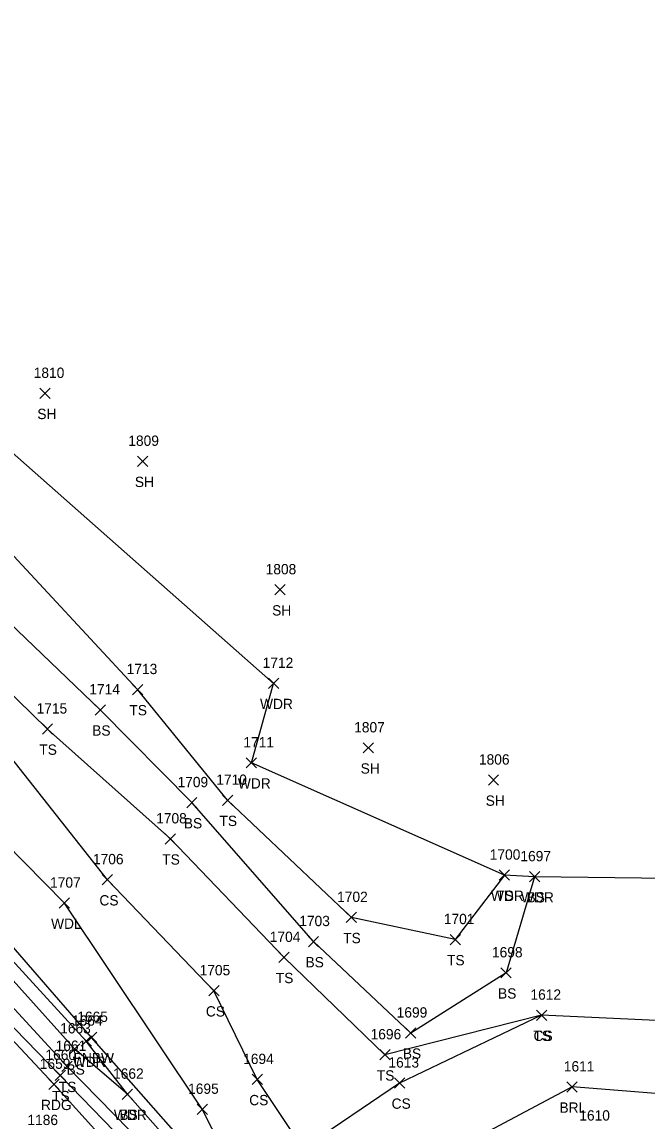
# Model space of a CAD drawing. Extents: x 1469310 to 1475157, y 493997 to 498873.
# Drawn here: x 1469508.8 to 1469630.2, y 498651.4 to 498864.7 of the extents above; entities that cross this region are included whole.
import ezdxf

# ---------------------------------------------------------------- set-up
doc = ezdxf.new("R2010")
doc.units = 0
for name, color, linetype in [('L_A', 7, 'Continuous'), ('L_I', 7, 'Continuous'), ('L_TIC', 7, 'Continuous'), ('LABL', 7, 'Continuous'), ('LAWA', 7, 'Continuous'), ('LELB', 7, 'Continuous'), ('LFNC', 7, 'Continuous'), ('P_A', 7, 'Continuous'), ('P_I', 7, 'Continuous'), ('P_TIC', 7, 'Continuous'), ('PEU', 7, 'Continuous')]:
    doc.layers.add(name, color=color, linetype=linetype)

msp = doc.modelspace()

# ---------------------------------------------------------------- linework, layer by layer
at = {"layer": 'L_TIC'}
for points in [[(1469512.26, 498791.65), (1469514.26, 498793.65)], [(1469514.26, 498791.65), (1469512.26, 498793.65)], [(1469531.21, 498778.46), (1469533.21, 498780.46)], [(1469533.21, 498778.46), (1469531.21, 498780.46)], [(1469557.88, 498753.52), (1469559.88, 498755.52)], [(1469559.88, 498753.52), (1469557.88, 498755.52)], [(1469556.66, 498735.35), (1469558.66, 498737.35)], [(1469558.66, 498735.35), (1469556.66, 498737.35)], [(1469530.24, 498734.14), (1469532.24, 498736.14)], [(1469532.24, 498734.14), (1469530.24, 498736.14)], [(1469522.97, 498730.2), (1469524.97, 498732.2)], [(1469524.97, 498730.2), (1469522.97, 498732.2)], [(1469512.73, 498726.48), (1469514.73, 498728.48)], [(1469514.73, 498726.48), (1469512.73, 498728.48)], [(1469575.08, 498722.83), (1469577.08, 498724.83)], [(1469577.08, 498722.83), (1469575.08, 498724.83)], [(1469552.35, 498719.92), (1469554.35, 498721.92)], [(1469554.35, 498719.92), (1469552.35, 498721.92)], [(1469599.38, 498716.58), (1469601.38, 498718.58)], [(1469601.38, 498716.58), (1469599.38, 498718.58)], [(1469540.77, 498712.19), (1469542.77, 498714.19)], [(1469542.77, 498712.19), (1469540.77, 498714.19)], [(1469547.73, 498712.65), (1469549.73, 498714.65)], [(1469549.73, 498712.65), (1469547.73, 498714.65)], [(1469536.62, 498705.16), (1469538.62, 498707.16)], [(1469538.62, 498705.16), (1469536.62, 498707.16)], [(1469524.38, 498697.23), (1469526.38, 498699.23)], [(1469526.38, 498697.23), (1469524.38, 498699.23)], [(1469601.51, 498698.12), (1469603.51, 498700.12)], [(1469603.51, 498698.12), (1469601.51, 498700.12)], [(1469601.51, 498698.12), (1469603.51, 498700.12)], [(1469603.51, 498698.12), (1469601.51, 498700.12)], [(1469607.35, 498697.81), (1469609.35, 498699.81)], [(1469609.35, 498697.81), (1469607.35, 498699.81)], [(1469607.35, 498697.81), (1469609.35, 498699.81)], [(1469609.35, 498697.81), (1469607.35, 498699.81)], [(1469516, 498692.69), (1469518, 498694.69)], [(1469518, 498692.69), (1469516, 498694.69)], [(1469571.77, 498689.91), (1469573.77, 498691.91)], [(1469573.77, 498689.91), (1469571.77, 498691.91)], [(1469564.41, 498685.22), (1469566.41, 498687.22)], [(1469566.41, 498685.22), (1469564.41, 498687.22)], [(1469591.94, 498685.61), (1469593.94, 498687.61)], [(1469593.94, 498685.61), (1469591.94, 498687.61)], [(1469558.68, 498682.15), (1469560.68, 498684.15)], [(1469560.68, 498682.15), (1469558.68, 498684.15)], [(1469601.82, 498679.15), (1469603.82, 498681.15)], [(1469603.82, 498679.15), (1469601.82, 498681.15)], [(1469545.06, 498675.67), (1469547.06, 498677.67)], [(1469547.06, 498675.67), (1469545.06, 498677.67)], [(1469608.73, 498670.93), (1469610.73, 498672.93)], [(1469610.73, 498670.93), (1469608.73, 498672.93)], [(1469608.73, 498670.93), (1469610.73, 498672.93)], [(1469610.73, 498670.93), (1469608.73, 498672.93)], [(1469583.31, 498667.47), (1469585.31, 498669.47)], [(1469585.31, 498667.47), (1469583.31, 498669.47)], [(1469520.27, 498665.89), (1469522.27, 498667.89)], [(1469522.27, 498665.89), (1469520.27, 498667.89)], [(1469521.29, 498666.62), (1469523.29, 498668.62)], [(1469523.29, 498666.62), (1469521.29, 498668.62)], [(1469517.98, 498664.39), (1469519.98, 498666.39)], [(1469519.98, 498664.39), (1469517.98, 498666.39)], [(1469578.3, 498663.24), (1469580.3, 498665.24)], [(1469580.3, 498663.24), (1469578.3, 498665.24)], [(1469516.52, 498661), (1469518.52, 498663)], [(1469518.52, 498661), (1469516.52, 498663)], [(1469515.21, 498659.23), (1469517.21, 498661.23)], [(1469517.21, 498659.23), (1469515.21, 498661.23)], [(1469553.48, 498658.45), (1469555.48, 498660.45)], [(1469555.48, 498658.45), (1469553.48, 498660.45)], [(1469581.14, 498657.76), (1469583.14, 498659.76)], [(1469583.14, 498657.76), (1469581.14, 498659.76)], [(1469614.65, 498657), (1469616.65, 498659)], [(1469616.65, 498657), (1469614.65, 498659)], [(1469528.26, 498655.59), (1469530.26, 498657.59)], [(1469530.26, 498655.59), (1469528.26, 498657.59)], [(1469528.26, 498655.59), (1469530.26, 498657.59)], [(1469530.26, 498655.59), (1469528.26, 498657.59)], [(1469542.79, 498652.66), (1469544.79, 498654.66)], [(1469544.79, 498652.66), (1469542.79, 498654.66)]]:
    msp.add_lwpolyline(points, dxfattribs=at)
at = {"layer": 'LABL'}
msp.add_lwpolyline([(1469804.95, 498565.12), (1469764.81, 498561.66), (1469749.08, 498576.22), (1469733.12, 498600.55), (1469716.5, 498617.67), (1469685.26, 498643.73), (1469661.91, 498654.33), (1469615.65, 498658), (1469588.27, 498643.44), (1469563.61, 498633.27)], dxfattribs=at)
at = {"layer": 'LAWA'}
for points in [[(1469639.57, 498698.43), (1469608.35, 498698.81), (1469602.51, 498699.12), (1469553.35, 498720.92), (1469557.66, 498736.35), (1469502.31, 498785.09), (1469489.42, 498793.62), (1469479.51, 498786.07), (1469473.54, 498782.36), (1469463.54, 498781.5), (1469427.61, 498811.79), (1469409.37, 498828.74), (1469393.62, 498848.43), (1469395.42, 498864.75)], [(1469550.26, 498635.87), (1469551.34, 498638.82), (1469543.79, 498653.66), (1469517, 498693.69), (1469493.7, 498717.29), (1469464.73, 498743.89), (1469442.45, 498767.36), (1469415.63, 498791.26), (1469396.51, 498809.17), (1469374.23, 498838.07)], [(1469550.26, 498635.87), (1469544.55, 498639.35), (1469529.26, 498656.59), (1469521.27, 498666.89), (1469499.1, 498691), (1469482.91, 498705.54), (1469469.32, 498718.6), (1469451.08, 498739.43), (1469431.27, 498758.58), (1469415.67, 498776.75), (1469392.18, 498799.73), (1469384.54, 498811.21)]]:
    msp.add_lwpolyline(points, dxfattribs=at)
at = {"layer": 'LELB'}
for points in [[(1469609.73, 498671.93), (1469579.3, 498664.24), (1469559.68, 498683.15), (1469537.62, 498706.16), (1469513.73, 498727.48), (1469478.41, 498761.91), (1469463.54, 498781.5), (1469454.7, 498803.05), (1469446.9, 498829.88), (1469451.16, 498846.1)], [(1469689.87, 498657.87), (1469664.2, 498669.39), (1469609.73, 498671.93), (1469582.14, 498658.76), (1469563.4, 498646.02), (1469554.48, 498659.45), (1469546.06, 498676.67), (1469525.38, 498698.23), (1469503.85, 498725.44), (1469472.45, 498754.54), (1469455.13, 498777.29), (1469419.87, 498802.33), (1469400.99, 498819.04), (1469383.05, 498844.76)], [(1469608.35, 498698.81), (1469602.82, 498680.15), (1469584.31, 498668.47), (1469565.41, 498686.22), (1469541.77, 498713.19), (1469523.97, 498731.2), (1469486.88, 498766.71), (1469473.54, 498782.36), (1469464.69, 498810.88), (1469465.59, 498843.26)], [(1469596.34, 498559.71), (1469578.35, 498585.4), (1469563.74, 498607.63), (1469555.37, 498620.37), (1469550.82, 498626.65), (1469541.68, 498637.32), (1469517.52, 498662), (1469494.24, 498687.27), (1469477.2, 498705.84), (1469448.36, 498735.3), (1469427.59, 498756.34), (1469413.62, 498771.3), (1469390.02, 498797.18), (1469364.14, 498823.89)], [(1469563.74, 498607.63), (1469555.09, 498616.5), (1469548.65, 498625.25), (1469539.23, 498636.49), (1469516.21, 498660.23), (1469492, 498685.05), (1469474.24, 498704.18), (1469446.06, 498733.49), (1469425.87, 498754.55), (1469411.99, 498769.1), (1469387.95, 498794.99), (1469362.09, 498822.05)], [(1469602.51, 498699.12), (1469592.94, 498686.61), (1469572.77, 498690.91), (1469548.73, 498713.65), (1469531.24, 498735.14), (1469494.62, 498774.5), (1469479.51, 498786.07)], [(1469529.26, 498656.59), (1469518.98, 498665.39), (1469497.29, 498689.45), (1469482.91, 498705.54)]]:
    msp.add_lwpolyline(points, dxfattribs=at)
at = {"layer": 'LFNC'}
msp.add_lwpolyline([(1469557.57, 498626.92), (1469550.26, 498635.87), (1469522.29, 498667.62), (1469500.25, 498692.91), (1469472.78, 498720.33), (1469454.31, 498738.91), (1469435.59, 498759.19), (1469416.3, 498780.92), (1469395.2, 498801.33), (1469384.54, 498811.21), (1469367.12, 498829.45)], dxfattribs=at)
at = {"layer": 'P_TIC'}
for points in [[(1469513.98, 498657.51), (1469515.98, 498659.51)], [(1469515.98, 498657.51), (1469513.98, 498659.51)]]:
    msp.add_lwpolyline(points, dxfattribs=at)
at = {"layer": 'PEU'}
msp.add_lwpolyline([(1469787.29, 498391.19), (1469770.79, 498403.19), (1469744.94, 498420.51), (1469711.23, 498443.77), (1469680.07, 498463.21), (1469651.58, 498483.41), (1469630.63, 498501.52), (1469612.52, 498523.24), (1469599.41, 498542.19), (1469591.57, 498556.6), (1469575.61, 498583.06), (1469557.31, 498607.49), (1469540.09, 498628.65), (1469536.24, 498634.99), (1469514.98, 498658.51), (1469490.83, 498684.27), (1469472.69, 498702.57), (1469444.89, 498732.16), (1469424.97, 498753.74), (1469411.28, 498767.74), (1469386.83, 498794.07), (1469360.47, 498820.44)], dxfattribs=at)

# ---------------------------------------------------------------- texts
at = {"layer": 'L_A'}
for s, p in [('SH', (1469511.75, 498787.65)), ('SH', (1469530.7, 498774.46)), ('SH', (1469557.37, 498749.52)), ('WDR', (1469555.02, 498731.35)), ('TS', (1469529.64, 498730.14)), ('BS', (1469522.41, 498726.2)), ('TS', (1469512.14, 498722.48)), ('SH', (1469574.57, 498718.83)), ('WDR', (1469550.71, 498715.92)), ('SH', (1469598.86, 498712.58)), ('BS', (1469540.21, 498708.19)), ('TS', (1469547.14, 498708.65)), ('TS', (1469536.02, 498701.16)), ('CS', (1469523.82, 498693.23)), ('WDR', (1469599.87, 498694.12)), ('TS', (1469600.92, 498694.12)), ('WDR', (1469605.72, 498693.81)), ('BS', (1469606.8, 498693.81)), ('WDL', (1469514.42, 498688.69)), ('TS', (1469571.18, 498685.91)), ('BS', (1469563.85, 498681.22)), ('TS', (1469591.35, 498681.61)), ('TS', (1469558.09, 498678.15)), ('BS', (1469601.26, 498675.15)), ('CS', (1469544.5, 498671.67)), ('TS', (1469608.14, 498666.93)), ('CS', (1469608.17, 498666.93)), ('FNBW', (1469518.77, 498662.62)), ('BS', (1469582.76, 498663.47)), ('WDR', (1469518.63, 498661.89)), ('BS', (1469517.42, 498660.39)), ('TS', (1469577.71, 498659.24)), ('TS', (1469515.93, 498657)), ('TS', (1469514.62, 498655.23)), ('CS', (1469552.92, 498654.45)), ('CS', (1469580.59, 498653.76)), ('BRL', (1469613.19, 498653)), ('WDR', (1469526.62, 498651.59)), ('BS', (1469527.7, 498651.59))]:
    msp.add_text(s, height=2, dxfattribs=at).set_placement(p)
at = {"layer": 'L_I'}
for s, p in [('1810', (1469511.05, 498795.65)), ('1809', (1469529.43, 498782.46)), ('1808', (1469556.11, 498757.52)), ('1713', (1469529.11, 498738.14)), ('1712', (1469555.53, 498739.35)), ('1714', (1469521.85, 498734.2)), ('1715', (1469511.6, 498730.48)), ('1807', (1469573.31, 498726.83)), ('1711', (1469551.79, 498723.92)), ('1806', (1469597.55, 498720.58)), ('1709', (1469538.99, 498716.19)), ('1710', (1469546.52, 498716.65)), ('1708', (1469534.84, 498709.16)), ('1706', (1469522.56, 498701.23)), ('1700', (1469599.65, 498702.12)), ('1700', (1469599.65, 498702.12)), ('1697', (1469605.61, 498701.81)), ('1697', (1469605.61, 498701.81)), ('1707', (1469514.23, 498696.69)), ('1702', (1469570, 498693.91)), ('1703', (1469562.64, 498689.22)), ('1701', (1469590.73, 498689.61)), ('1704', (1469556.91, 498686.15)), ('1698', (1469600.08, 498683.15)), ('1705', (1469543.28, 498679.67)), ('1612', (1469607.56, 498674.93)), ('1612', (1469607.56, 498674.93)), ('1699', (1469581.57, 498671.47)), ('1664', (1469518.48, 498669.89)), ('1665', (1469519.51, 498670.62)), ('1663', (1469516.19, 498668.39)), ('1696', (1469576.5, 498667.24)), ('1661', (1469515.3, 498665)), ('1660', (1469513.33, 498663.23)), ('1694', (1469551.74, 498662.45)), ('1613', (1469579.97, 498661.76)), ('1611', (1469614.04, 498661)), ('1662', (1469526.47, 498659.59)), ('1662', (1469526.47, 498659.59)), ('1695', (1469541.05, 498656.66)), ('1610', (1469617.05, 498651.47))]:
    msp.add_text(s, height=2, dxfattribs=at).set_placement(p)
at = {"layer": 'P_A'}
msp.add_text('RDG', height=2, dxfattribs=at).set_placement((1469512.47, 498653.51))
at = {"layer": 'P_I'}
for s, p in [('1659', (1469512.23, 498661.51)), ('1186', (1469509.83, 498650.6))]:
    msp.add_text(s, height=2, dxfattribs=at).set_placement(p)

doc.saveas('drawing.dxf')
